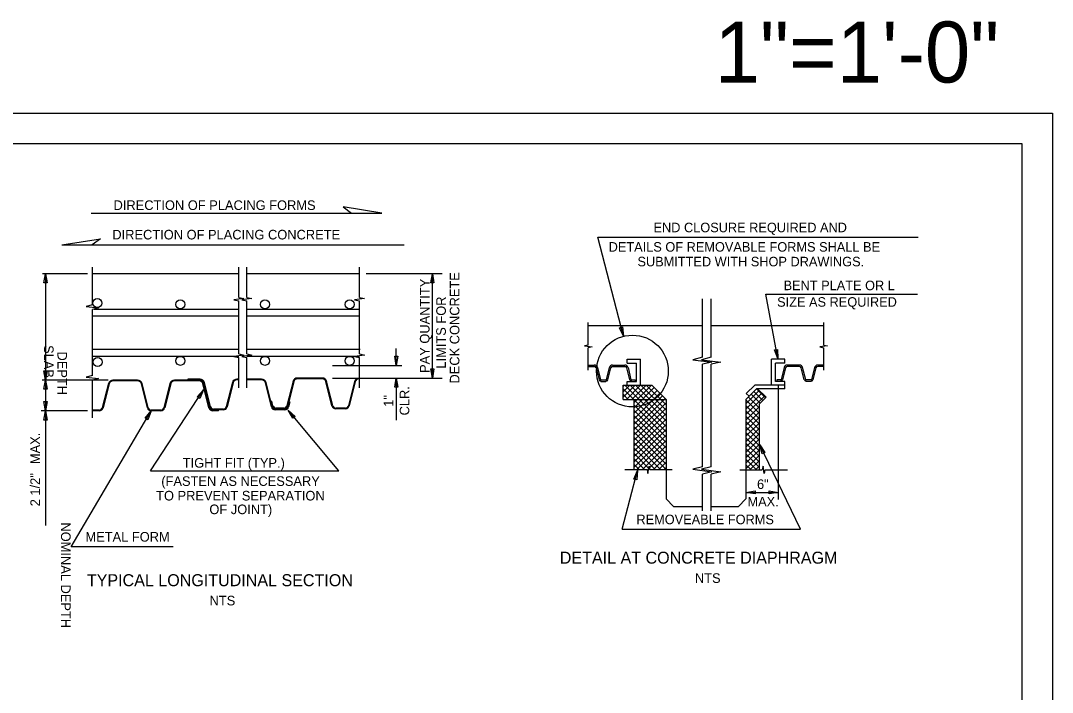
# Model space of a CAD drawing. Extents: x 0 to 34, y 0 to 23.5.
# Drawn here: x 17.1 to 34, y 12.5 to 23.51 of the extents above; entities that cross this region are included whole.
import ezdxf

# ---------------------------------------------------------------- set-up
doc = ezdxf.new("R2010")
doc.units = 0
for name, color, linetype in [('BORDER_ANNO_Cutsheet', 7, 'Continuous'), ('BRDG_ANNO_Anno-Sheet', 7, 'Continuous'), ('BRDG_ANNO_General-Notes', 7, 'Continuous'), ('BRDG_BASE_Dtlctrln', 7, 'Continuous'), ('BRDG_BASE_Obj-Line', 7, 'Continuous'), ('BRDG_BASE_Rebar', 7, 'Continuous')]:
    doc.layers.add(name, color=color, linetype=linetype)

msp = doc.modelspace()

# ---------------------------------------------------------------- linework, layer by layer
at = {"layer": 'BORDER_ANNO_Cutsheet'}
msp.add_lwpolyline([(0, 22), (34, 22), (34, 0), (0, 0)], close=True, dxfattribs=at)
at = {"layer": 'BRDG_ANNO_Anno-Sheet'}
msp.add_lwpolyline([(1.5, 21.5), (33.5, 21.5), (33.5, 0.5), (1.5, 0.5)], close=True, dxfattribs=at)
at = {"layer": 'BRDG_ANNO_General-Notes'}
for p, q in [((18.252, 20.359), (23.016, 20.359)), ((26.551, 19.967), (31.804, 19.967)), ((26.972, 18.34), (26.551, 19.967)), ((17.772, 19.838), (23.379, 19.838)), ((18.193, 19.366), (17.457, 19.366)), ((17.48, 19.215), (17.504, 19.366)), ((17.504, 19.366), (17.504, 17.623)), ((17.504, 19.366), (17.53, 19.215)), ((22.759, 19.367), (24.006, 19.367)), ((23.817, 19.216), (23.843, 19.366)), ((23.843, 17.655), (23.843, 19.367)), ((23.843, 19.366), (23.867, 19.216)), ((17.53, 19.215), (17.48, 19.215)), ((23.867, 19.216), (23.817, 19.216)), ((29.304, 19.029), (31.791, 19.029)), ((29.501, 17.974), (29.304, 19.029)), ((26.91, 18.481), (26.959, 18.493)), ((26.972, 18.34), (26.91, 18.481)), ((26.959, 18.493), (26.972, 18.34)), ((23.252, 17.862), (23.252, 18.139)), ((29.449, 18.117), (29.498, 18.124)), ((29.501, 17.974), (29.449, 18.117)), ((29.498, 18.124), (29.501, 17.974)), ((23.227, 18.013), (23.277, 18.013)), ((23.252, 17.862), (23.227, 18.013)), ((23.277, 18.013), (23.252, 17.862)), ((17.48, 17.774), (17.53, 17.774)), ((17.504, 17.623), (17.48, 17.774)), ((17.53, 17.774), (17.504, 17.623)), ((22.208, 17.862), (23.342, 17.862)), ((23.817, 17.807), (23.867, 17.807)), ((23.843, 17.655), (23.817, 17.807)), ((23.867, 17.807), (23.843, 17.655)), ((18.531, 17.623), (17.449, 17.623)), ((17.48, 17.471), (17.504, 17.623)), ((17.504, 17.623), (17.504, 17.119)), ((17.504, 17.623), (17.53, 17.471)), ((22.208, 17.655), (24.006, 17.655)), ((23.227, 17.505), (23.252, 17.655)), ((23.252, 17.655), (23.252, 16.966)), ((23.252, 17.655), (23.277, 17.505)), ((17.53, 17.471), (17.48, 17.471)), ((19.223, 16.136), (20.095, 17.462)), ((19.992, 17.35), (20.095, 17.462)), ((20.095, 17.462), (20.033, 17.323)), ((23.277, 17.505), (23.227, 17.505)), ((17.48, 17.27), (17.53, 17.27)), ((17.504, 17.119), (17.48, 17.27)), ((17.53, 17.27), (17.504, 17.119)), ((20.033, 17.323), (19.992, 17.35)), ((18.193, 17.119), (17.435, 17.119)), ((17.48, 16.967), (17.504, 17.119)), ((17.504, 17.119), (17.504, 15.241)), ((17.504, 17.119), (17.53, 16.967)), ((17.925, 14.891), (19.236, 17.116)), ((19.138, 16.998), (19.236, 17.116)), ((19.236, 17.116), (19.181, 16.972)), ((22.311, 16.136), (21.481, 17.129)), ((21.559, 16.997), (21.481, 17.129)), ((21.481, 17.129), (21.598, 17.028)), ((17.53, 16.967), (17.48, 16.967)), ((19.181, 16.972), (19.138, 16.998)), ((21.598, 17.028), (21.559, 16.997)), ((29.872, 15.178), (29.206, 16.561)), ((29.247, 16.416), (29.206, 16.561)), ((29.206, 16.561), (29.291, 16.438)), ((29.291, 16.438), (29.247, 16.416)), ((19.223, 16.136), (22.311, 16.136)), ((26.952, 15.178), (27.203, 16.138)), ((27.141, 15.998), (27.203, 16.138)), ((27.203, 16.138), (27.19, 15.985)), ((27.19, 15.985), (27.141, 15.998)), ((28.98, 15.781), (29.129, 15.808)), ((28.98, 15.781), (29.508, 15.781)), ((29.129, 15.757), (28.98, 15.781)), ((29.129, 15.808), (29.129, 15.757)), ((29.358, 15.757), (29.358, 15.808)), ((29.358, 15.808), (29.508, 15.781)), ((29.508, 15.781), (29.358, 15.757)), ((26.952, 15.178), (29.872, 15.178)), ((19.594, 14.891), (17.925, 14.891))]:
    msp.add_line(p, q, dxfattribs=at)
for points in [[(23.016, 20.359), (22.383, 20.463), (22.52, 20.359)], [(17.772, 19.838), (18.405, 19.94), (18.268, 19.838)]]:
    msp.add_lwpolyline(points, dxfattribs=at)
msp.add_circle((27.12, 17.771), 0.588, dxfattribs=at)
at = {"layer": 'BRDG_BASE_Dtlctrln'}
msp.add_line((29.508, 17.54), (29.508, 15.665), dxfattribs=at)
at = {"layer": 'BRDG_BASE_Obj-Line'}
for p, q in [((18.274, 18.856), (18.274, 19.473)), ((20.672, 18.979), (20.672, 19.473)), ((20.803, 18.979), (20.803, 19.473)), ((22.651, 18.979), (22.651, 19.473)), ((20.672, 19.366), (18.274, 19.366)), ((22.651, 19.366), (20.803, 19.366)), ((20.753, 18.959), (20.591, 18.939)), ((20.591, 18.939), (20.672, 18.919)), ((20.672, 18.979), (20.753, 18.959)), ((20.883, 18.959), (20.722, 18.939)), ((20.722, 18.939), (20.803, 18.919)), ((20.803, 18.979), (20.883, 18.959)), ((22.732, 18.959), (22.57, 18.939)), ((22.57, 18.939), (22.651, 18.919)), ((22.651, 18.979), (22.732, 18.959)), ((28.268, 17.996), (28.268, 18.953)), ((28.411, 17.996), (28.411, 18.953)), ((18.274, 18.856), (18.172, 18.83)), ((18.172, 18.83), (18.374, 18.806)), ((18.374, 18.806), (18.274, 18.78)), ((18.274, 17.697), (18.274, 18.78)), ((20.672, 18.052), (20.672, 18.919)), ((20.803, 18.052), (20.803, 18.919)), ((22.651, 18.052), (22.651, 18.919)), ((26.396, 18.517), (28.268, 18.517)), ((26.398, 18.197), (26.398, 18.564)), ((28.411, 18.517), (30.256, 18.517)), ((30.254, 18.197), (30.254, 18.564)), ((26.398, 18.197), (26.334, 18.183)), ((26.334, 18.183), (26.46, 18.166)), ((26.46, 18.166), (26.398, 18.151)), ((26.398, 17.784), (26.398, 18.151)), ((30.318, 18.183), (30.192, 18.166)), ((30.192, 18.166), (30.254, 18.151)), ((30.254, 18.197), (30.318, 18.183)), ((30.254, 17.784), (30.254, 18.151)), ((20.753, 18.032), (20.591, 18.011)), ((20.591, 18.011), (20.672, 17.992)), ((20.672, 18.052), (20.753, 18.032)), ((20.672, 17.498), (20.672, 17.992)), ((20.883, 18.032), (20.722, 18.011)), ((20.722, 18.011), (20.803, 17.992)), ((20.803, 18.052), (20.883, 18.032)), ((20.803, 17.498), (20.803, 17.992)), ((22.732, 18.032), (22.57, 18.011)), ((22.57, 18.011), (22.651, 17.992)), ((22.651, 18.052), (22.732, 18.032)), ((22.651, 17.498), (22.651, 17.992)), ((27.036, 17.966), (27.252, 17.966)), ((27.036, 17.902), (27.036, 17.966)), ((27.252, 17.54), (27.252, 17.966)), ((28.268, 17.996), (28.111, 17.956)), ((28.111, 17.956), (28.424, 17.917)), ((28.411, 17.996), (28.253, 17.956)), ((28.253, 17.956), (28.566, 17.917)), ((28.424, 17.917), (28.268, 17.881)), ((28.566, 17.917), (28.411, 17.881)), ((29.4, 17.54), (29.4, 17.966)), ((29.616, 17.966), (29.4, 17.966)), ((29.616, 17.902), (29.616, 17.966)), ((26.396, 17.868), (26.497, 17.868)), ((26.396, 17.846), (26.497, 17.846)), ((26.526, 17.823), (26.575, 17.627)), ((26.549, 17.828), (26.598, 17.629)), ((26.694, 17.629), (26.743, 17.828)), ((26.716, 17.627), (26.765, 17.823)), ((26.795, 17.868), (26.895, 17.868)), ((26.795, 17.846), (26.895, 17.846)), ((26.895, 17.868), (26.997, 17.868)), ((26.895, 17.846), (26.997, 17.846)), ((27.026, 17.823), (27.075, 17.627)), ((27.036, 17.902), (27.189, 17.902)), ((27.048, 17.828), (27.097, 17.629)), ((27.189, 17.602), (27.189, 17.902)), ((28.268, 16.2), (28.268, 17.881)), ((28.411, 16.2), (28.411, 17.881)), ((29.464, 17.602), (29.464, 17.902)), ((29.616, 17.902), (29.464, 17.902)), ((29.604, 17.828), (29.555, 17.629)), ((29.626, 17.823), (29.577, 17.627)), ((29.757, 17.868), (29.656, 17.868)), ((29.757, 17.846), (29.656, 17.846)), ((29.857, 17.868), (29.757, 17.868)), ((29.857, 17.846), (29.757, 17.846)), ((29.936, 17.627), (29.887, 17.823)), ((29.959, 17.629), (29.909, 17.828)), ((30.103, 17.828), (30.054, 17.629)), ((30.126, 17.823), (30.077, 17.627)), ((30.256, 17.868), (30.156, 17.868)), ((30.256, 17.846), (30.156, 17.846)), ((18.274, 17.697), (18.172, 17.672)), ((18.172, 17.672), (18.374, 17.646)), ((18.374, 17.646), (18.274, 17.622)), ((18.274, 17.004), (18.274, 17.622)), ((18.812, 17.623), (18.609, 17.623)), ((18.812, 17.61), (18.609, 17.61)), ((19.015, 17.623), (18.812, 17.623)), ((19.015, 17.61), (18.812, 17.61)), ((19.82, 17.623), (19.617, 17.623)), ((19.82, 17.61), (19.617, 17.61)), ((20.022, 17.623), (19.82, 17.623)), ((20.022, 17.61), (19.82, 17.61)), ((20.038, 17.638), (19.835, 17.638)), ((19.835, 17.638), (19.835, 17.626)), ((20.038, 17.626), (19.835, 17.626)), ((20.198, 17.182), (20.099, 17.578)), ((20.21, 17.182), (20.111, 17.581)), ((20.567, 17.581), (20.467, 17.182)), ((20.579, 17.578), (20.48, 17.182)), ((20.672, 17.638), (20.64, 17.638)), ((20.672, 17.626), (20.64, 17.626)), ((20.843, 17.638), (20.803, 17.638)), ((20.843, 17.626), (20.803, 17.626)), ((21.046, 17.638), (20.843, 17.638)), ((21.046, 17.626), (20.843, 17.626)), ((21.205, 17.182), (21.107, 17.578)), ((21.218, 17.182), (21.119, 17.581)), ((21.56, 17.601), (21.46, 17.203)), ((21.571, 17.595), (21.473, 17.2)), ((21.835, 17.655), (21.632, 17.655)), ((21.835, 17.643), (21.632, 17.643)), ((22.038, 17.655), (21.835, 17.655)), ((22.038, 17.643), (21.835, 17.643)), ((22.198, 17.2), (22.099, 17.595)), ((22.211, 17.2), (22.111, 17.598)), ((22.567, 17.601), (22.468, 17.203)), ((22.579, 17.595), (22.481, 17.2)), ((22.651, 17.655), (22.64, 17.655)), ((22.651, 17.643), (22.64, 17.643)), ((26.605, 17.624), (26.644, 17.624)), ((26.605, 17.602), (26.644, 17.602)), ((26.644, 17.624), (26.687, 17.624)), ((26.644, 17.602), (26.687, 17.602)), ((27.036, 17.602), (27.189, 17.602)), ((27.036, 17.54), (27.036, 17.602)), ((27.105, 17.624), (27.164, 17.624)), ((27.105, 17.602), (27.164, 17.602)), ((27.164, 17.624), (27.164, 17.602)), ((29.616, 17.602), (29.464, 17.602)), ((29.547, 17.624), (29.488, 17.624)), ((29.488, 17.624), (29.488, 17.602)), ((29.547, 17.602), (29.488, 17.602)), ((29.616, 17.54), (29.616, 17.602)), ((30.008, 17.624), (29.969, 17.624)), ((30.008, 17.602), (29.969, 17.602)), ((30.047, 17.624), (30.008, 17.624)), ((30.047, 17.602), (30.008, 17.602)), ((18.536, 17.566), (18.436, 17.167)), ((18.548, 17.563), (18.45, 17.167)), ((19.175, 17.167), (19.076, 17.563)), ((19.188, 17.167), (19.089, 17.566)), ((19.544, 17.566), (19.444, 17.167)), ((19.556, 17.563), (19.458, 17.167)), ((20.183, 17.167), (20.083, 17.563)), ((20.196, 17.167), (20.096, 17.566)), ((26.969, 17.307), (26.969, 17.54)), ((26.969, 17.54), (27.439, 17.54)), ((26.969, 17.518), (26.989, 17.54)), ((26.969, 17.432), (27.077, 17.54)), ((26.969, 17.343), (27.166, 17.54)), ((27.141, 17.307), (26.969, 17.479)), ((27.673, 16.864), (26.994, 17.54)), ((27.021, 17.307), (27.254, 17.54)), ((27.036, 17.54), (27.252, 17.54)), ((27.673, 16.953), (27.082, 17.54)), ((27.11, 17.307), (27.343, 17.54)), ((27.141, 17.25), (27.432, 17.54)), ((27.141, 17.161), (27.479, 17.499)), ((27.141, 17.073), (27.523, 17.454)), ((27.141, 16.984), (27.567, 17.41)), ((27.673, 17.041), (27.171, 17.54)), ((27.673, 17.127), (27.259, 17.54)), ((27.673, 17.215), (27.348, 17.54)), ((27.673, 17.304), (27.436, 17.54)), ((27.673, 17.307), (27.439, 17.54)), ((28.98, 17.233), (29.198, 17.451)), ((28.986, 17.402), (29.127, 17.54)), ((29.031, 17.358), (29.152, 17.479)), ((29.255, 17.287), (29.107, 17.435)), ((29.616, 17.54), (29.127, 17.54)), ((29.616, 17.479), (29.152, 17.479)), ((29.299, 17.331), (29.152, 17.479)), ((29.309, 17.341), (29.171, 17.479)), ((29.616, 17.54), (29.4, 17.54)), ((29.616, 17.479), (29.616, 17.54)), ((21.213, 17.275), (21.201, 17.272)), ((21.219, 17.2), (21.201, 17.272)), ((21.232, 17.203), (21.213, 17.275)), ((21.496, 17.267), (21.475, 17.182)), ((21.508, 17.264), (21.488, 17.182)), ((21.496, 17.267), (21.508, 17.264)), ((27.053, 17.307), (26.969, 17.39)), ((26.969, 17.307), (27.673, 17.307)), ((27.141, 16.895), (27.612, 17.366)), ((27.141, 16.807), (27.656, 17.322)), ((27.141, 17.307), (27.141, 16.155)), ((27.673, 16.775), (27.141, 17.307)), ((27.141, 16.718), (27.673, 17.25)), ((27.673, 17.307), (27.673, 16.151)), ((28.98, 17.144), (29.242, 17.407)), ((28.98, 17.056), (29.287, 17.363)), ((28.98, 17.307), (29.031, 17.358)), ((28.98, 17.307), (28.98, 16.151)), ((29.196, 17.08), (28.98, 17.297)), ((29.031, 17.358), (28.986, 17.402)), ((29.196, 17.169), (29.019, 17.346)), ((29.211, 17.243), (29.063, 17.39)), ((29.196, 17.228), (29.309, 17.341)), ((18.389, 17.132), (18.274, 17.132)), ((18.389, 17.119), (18.274, 17.119)), ((19.316, 17.132), (19.236, 17.132)), ((19.316, 17.119), (19.236, 17.119)), ((19.397, 17.132), (19.316, 17.132)), ((19.397, 17.119), (19.316, 17.119)), ((20.339, 17.132), (20.244, 17.132)), ((20.339, 17.119), (20.244, 17.119)), ((20.339, 17.147), (20.259, 17.147)), ((20.339, 17.135), (20.259, 17.135)), ((20.419, 17.147), (20.339, 17.147)), ((20.419, 17.135), (20.339, 17.135)), ((20.339, 17.119), (20.339, 17.132)), ((21.347, 17.147), (21.266, 17.147)), ((21.347, 17.135), (21.266, 17.135)), ((21.347, 17.164), (21.28, 17.164)), ((21.347, 17.151), (21.28, 17.151)), ((21.411, 17.164), (21.347, 17.164)), ((21.411, 17.151), (21.347, 17.151)), ((21.427, 17.147), (21.347, 17.147)), ((21.427, 17.135), (21.347, 17.135)), ((22.339, 17.164), (22.259, 17.164)), ((22.339, 17.151), (22.259, 17.151)), ((22.419, 17.164), (22.339, 17.164)), ((22.419, 17.151), (22.339, 17.151)), ((27.673, 16.687), (27.141, 17.218)), ((27.141, 16.63), (27.673, 17.161)), ((27.673, 16.598), (27.141, 17.13)), ((27.141, 16.541), (27.673, 17.073)), ((29.196, 16.992), (28.98, 17.208)), ((28.98, 16.967), (29.196, 17.184)), ((29.196, 16.903), (28.98, 17.12)), ((28.98, 16.879), (29.196, 17.095)), ((29.196, 17.228), (29.196, 16.155)), ((27.673, 16.51), (27.141, 17.041)), ((27.141, 16.453), (27.673, 16.984)), ((27.673, 16.421), (27.141, 16.953)), ((29.196, 16.815), (28.98, 17.031)), ((28.98, 16.79), (29.196, 17.007)), ((29.196, 16.726), (28.98, 16.943)), ((28.98, 16.702), (29.196, 16.918)), ((27.141, 16.364), (27.673, 16.895)), ((27.673, 16.333), (27.141, 16.864)), ((27.141, 16.278), (27.673, 16.81)), ((27.673, 16.244), (27.141, 16.775)), ((29.196, 16.64), (28.98, 16.854)), ((28.98, 16.613), (29.196, 16.83)), ((29.196, 16.551), (28.98, 16.766)), ((28.98, 16.524), (29.196, 16.741)), ((27.141, 16.19), (27.673, 16.721)), ((27.673, 16.155), (27.141, 16.687)), ((27.587, 16.152), (27.141, 16.598)), ((27.195, 16.155), (27.673, 16.633)), ((29.196, 16.462), (28.98, 16.677)), ((28.98, 16.436), (29.196, 16.652)), ((29.196, 16.374), (28.98, 16.588)), ((27.498, 16.152), (27.141, 16.51)), ((27.41, 16.152), (27.141, 16.423)), ((27.284, 16.155), (27.673, 16.544)), ((27.371, 16.155), (27.673, 16.456)), ((28.98, 16.347), (29.196, 16.564)), ((29.196, 16.285), (28.98, 16.502)), ((28.98, 16.259), (29.196, 16.475)), ((29.196, 16.197), (28.98, 16.413)), ((27.318, 16.155), (27.141, 16.335)), ((27.23, 16.155), (27.141, 16.246)), ((27.459, 16.152), (27.673, 16.367)), ((27.548, 16.152), (27.673, 16.278)), ((28.98, 16.17), (29.196, 16.387)), ((29.149, 16.155), (28.98, 16.325)), ((29.06, 16.155), (28.98, 16.236)), ((29.05, 16.155), (29.196, 16.298)), ((27.361, 16.151), (26.994, 16.151)), ((27.141, 16.155), (27.141, 16.157)), ((27.361, 16.151), (27.375, 16.089)), ((27.375, 16.089), (27.392, 16.212)), ((27.392, 16.212), (27.407, 16.151)), ((27.774, 16.151), (27.407, 16.151)), ((27.633, 16.152), (27.673, 16.19)), ((27.673, 16.151), (27.673, 15.678)), ((28.268, 16.2), (28.111, 16.16)), ((28.111, 16.16), (28.424, 16.121)), ((28.411, 16.2), (28.253, 16.16)), ((28.253, 16.16), (28.566, 16.121)), ((28.424, 16.121), (28.268, 16.082)), ((28.268, 15.478), (28.268, 16.082)), ((28.566, 16.121), (28.411, 16.082)), ((28.411, 15.478), (28.411, 16.082)), ((28.878, 16.151), (29.245, 16.151)), ((28.98, 16.151), (28.98, 15.678)), ((29.142, 16.155), (29.196, 16.21)), ((29.262, 16.212), (29.245, 16.151)), ((29.277, 16.089), (29.262, 16.212)), ((29.291, 16.151), (29.277, 16.089)), ((29.291, 16.151), (29.659, 16.151)), ((27.796, 15.552), (27.673, 15.678)), ((27.796, 15.552), (28.268, 15.552)), ((28.411, 15.552), (28.857, 15.552)), ((28.857, 15.552), (28.98, 15.678))]:
    msp.add_line(p, q, dxfattribs=at)
for centre, radius, start, end in [((26.496, 17.815), 0.0531, 13.9633, 90), ((26.496, 17.815), 0.0312, 13.9633, 90), ((26.795, 17.815), 0.0531, 90, 166.0367), ((26.795, 17.815), 0.0312, 90, 166.0367), ((26.996, 17.815), 0.0531, 13.9633, 90), ((26.996, 17.815), 0.0312, 13.9633, 90), ((29.656, 17.815), 0.0531, 90, 166.0367), ((29.656, 17.815), 0.0312, 90, 166.0367), ((29.857, 17.815), 0.0531, 13.9633, 90), ((29.857, 17.815), 0.0312, 13.9633, 90), ((30.156, 17.815), 0.0531, 90, 166.0367), ((30.156, 17.815), 0.0312, 90, 166.0367), ((18.61, 17.547), 0.0756, 90, 166.0367), ((18.61, 17.547), 0.063, 90, 166.0367), ((19.015, 17.547), 0.0756, 13.9633, 90), ((19.015, 17.547), 0.063, 13.9633, 90), ((19.617, 17.547), 0.0756, 90, 166.0367), ((19.617, 17.547), 0.063, 90, 166.0367), ((20.023, 17.547), 0.0756, 13.9633, 90), ((20.023, 17.547), 0.063, 13.9633, 90), ((20.038, 17.563), 0.0756, 13.9633, 90), ((20.038, 17.563), 0.063, 13.9633, 90), ((20.64, 17.563), 0.0756, 89.7446, 166.0367), ((20.64, 17.563), 0.063, 90, 166.0367), ((21.046, 17.563), 0.0756, 13.9633, 90), ((21.046, 17.563), 0.063, 13.9633, 90), ((21.633, 17.58), 0.0756, 90, 166.0367), ((21.633, 17.58), 0.063, 90, 166.0367), ((22.038, 17.58), 0.0756, 13.9633, 90), ((22.038, 17.58), 0.063, 13.9633, 90), ((22.64, 17.58), 0.0748, 90, 164.1569), ((22.64, 17.58), 0.063, 90.1763, 166.0367), ((26.606, 17.634), 0.0312, 194.0453, 270), ((26.606, 17.634), 0.00937, 194.0453, 270), ((26.685, 17.634), 0.00937, 270, 346.0067), ((26.685, 17.634), 0.0312, 270, 346.0067), ((27.106, 17.634), 0.0312, 194.0453, 270), ((27.106, 17.634), 0.00937, 194.0453, 270), ((29.546, 17.634), 0.00937, 270, 345.9547), ((29.546, 17.634), 0.0312, 270, 345.9547), ((29.967, 17.634), 0.0312, 193.9933, 270), ((29.967, 17.634), 0.00937, 193.9933, 270), ((30.046, 17.634), 0.00937, 270, 345.9547), ((30.046, 17.634), 0.0312, 270, 345.9547), ((18.388, 17.182), 0.0504, 270, 345.9547), ((18.388, 17.182), 0.063, 270, 345.9547), ((19.236, 17.182), 0.063, 193.9933, 270), ((19.236, 17.182), 0.0504, 193.9933, 270), ((19.396, 17.182), 0.0504, 270, 345.9547), ((19.396, 17.182), 0.063, 270, 345.9547), ((20.244, 17.182), 0.063, 193.9933, 270), ((20.244, 17.182), 0.0504, 193.9933, 270), ((20.259, 17.198), 0.063, 193.9933, 270), ((20.259, 17.198), 0.0504, 193.9933, 270), ((20.419, 17.198), 0.0504, 270, 345.9547), ((20.419, 17.198), 0.063, 270, 345.9547), ((21.267, 17.198), 0.063, 193.9933, 270), ((21.267, 17.198), 0.0504, 193.9933, 270), ((21.281, 17.215), 0.063, 193.9933, 270), ((21.281, 17.215), 0.0504, 193.9933, 270), ((21.411, 17.215), 0.0504, 270, 345.9547), ((21.411, 17.215), 0.063, 270, 345.9547), ((21.427, 17.198), 0.0504, 270, 345.9547), ((21.427, 17.198), 0.063, 270, 345.9547), ((22.259, 17.215), 0.063, 193.9933, 270), ((22.259, 17.215), 0.0504, 193.9933, 270), ((22.419, 17.215), 0.0504, 270, 345.9547), ((22.419, 17.215), 0.063, 270, 345.9547)]:
    msp.add_arc(centre, radius, start, end, dxfattribs=at)
at = {"layer": 'BRDG_BASE_Rebar'}
for p, q in [((18.3, 18.787), (20.672, 18.787)), ((20.803, 18.787), (22.651, 18.787)), ((18.274, 18.674), (20.672, 18.674)), ((20.803, 18.674), (22.651, 18.674)), ((18.274, 18.127), (20.672, 18.127)), ((20.803, 18.127), (22.658, 18.127)), ((18.274, 18.013), (20.672, 18.013)), ((20.803, 18.013), (22.651, 18.013))]:
    msp.add_line(p, q, dxfattribs=at)
for centre in [(18.353, 18.884), (19.715, 18.863), (21.101, 18.863), (22.487, 18.863), (18.359, 17.919), (19.715, 17.938), (21.101, 17.938), (22.487, 17.938)]:
    msp.add_circle(centre, 0.0738, dxfattribs=at)

# ---------------------------------------------------------------- texts
at = {"layer": 'BRDG_ANNO_Anno-Sheet'}
msp.add_text('1"=1\'-0"', height=1, dxfattribs=at).set_placement((28.467, 22.5))
at = {"layer": 'BRDG_ANNO_General-Notes'}
for s, height, p in [('DIRECTION OF PLACING FORMS', 0.15745, (18.62, 20.411)), ('END CLOSURE REQUIRED AND', 0.15622, (27.466, 20.046)), ('DIRECTION OF PLACING CONCRETE ', 0.15745, (18.6, 19.928)), ('DETAILS OF REMOVABLE FORMS SHALL BE ', 0.15622, (26.731, 19.728)), ('SUBMITTED WITH SHOP DRAWINGS.', 0.15622, (27.203, 19.487)), ('BENT PLATE OR L', 0.15622, (29.597, 19.096)), ('SIZE AS REQUIRED', 0.15622, (29.491, 18.825)), ('TIGHT FIT (TYP.)', 0.15745, (19.754, 16.187)), ('(FASTEN AS NECESSARY', 0.15745, (19.402, 15.888)), ('6"', 0.1565, (29.162, 15.838)), ('TO PREVENT SEPARATION', 0.15745, (19.318, 15.649)), ('OF JOINT)', 0.1574, (20.19, 15.425)), ('MAX.', 0.1562, (29.006, 15.552)), ('REMOVEABLE FORMS', 0.15622, (27.186, 15.26)), ('METAL FORM', 0.1574, (18.16, 14.975)), ('DETAIL AT CONCRETE DIAPHRAGM', 0.19681, (25.931, 14.613)), ('TYPICAL LONGITUDINAL SECTION', 0.19681, (18.183, 14.244)), ('NTS', 0.1575, (28.144, 14.298)), ('NTS', 0.1575, (20.193, 13.929))]:
    msp.add_text(s, height=height, dxfattribs=at).set_placement(p)
for s, height, rotation, p in [('PAY QUANTITY', 0.15746, 90, (23.796, 17.74)), ('DECK CONCRETE', 0.15746, 90, (24.286, 17.566)), ('LIMITS FOR', 0.1575, 90, (24.064, 17.811)), ('SLAB ', 0.1574, 270, (17.48, 18.196)), ('DEPTH', 0.1574, 270, (17.701, 18.091)), ('CLR.', 0.1574, 90, (23.465, 17.043)), ('1"', 0.1574, 90, (23.203, 17.185)), ('MAX.', 0.1574, 90, (17.414, 16.245)), ('2 1/2"', 0.1574, 90, (17.414, 15.554)), ('NOMINAL DEPTH', 0.15745, 270, (17.759, 15.289))]:
    msp.add_text(s, height=height, rotation=rotation, dxfattribs=at).set_placement(p)

doc.saveas('drawing.dxf')
